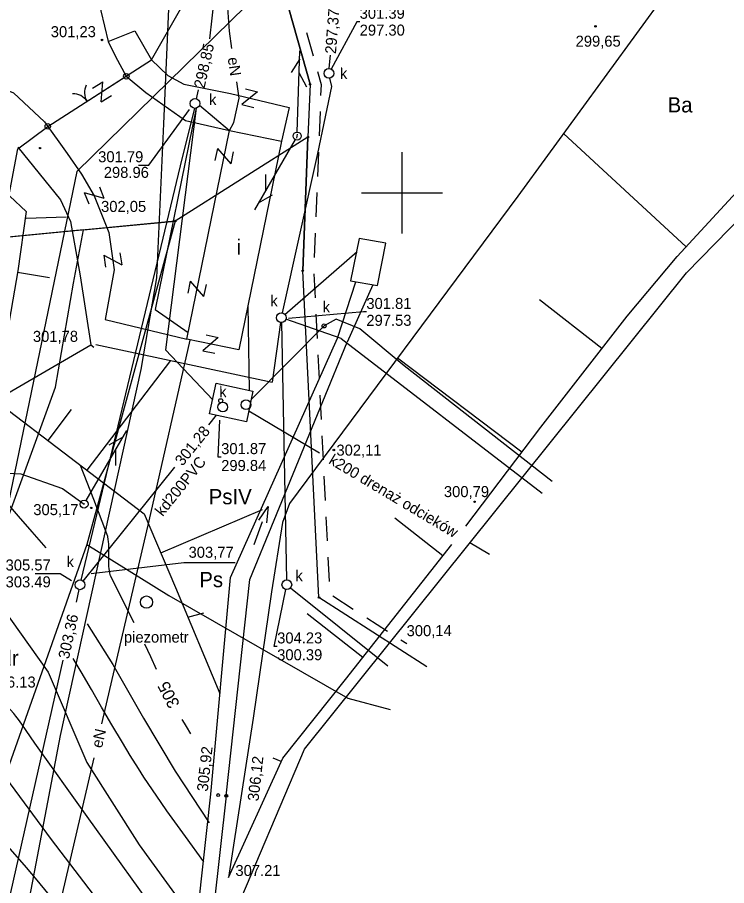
# Model space of a CAD drawing. Extents: x 7477803 to 7478145, y 5500698 to 5500984.
# Drawn here: x 7478026.3 to 7478070, y 5500757.3 to 5500810.8 of the extents above; entities that cross this region are included whole.
import ezdxf

# ---------------------------------------------------------------- set-up
doc = ezdxf.new("R2010")
doc.units = 0
for name, color, linetype in [('203-Punkt załamania granicy działki nie stabilizowany', 7, 'Continuous'), ('budynek', 7, 'Continuous'), ('e_opisy', 7, 'Continuous'), ('e_Proj', 7, 'Continuous'), ('eNN', 7, 'Continuous'), ('funkcja_kondygnacja', 7, 'Continuous'), ('gr_dzialki', 7, 'Continuous'), ('gr_klasy', 7, 'Continuous'), ('gr_uzytek', 7, 'Continuous'), ('k', 7, 'Continuous'), ('k_elem_naziemne', 7, 'Continuous'), ('k_opis', 7, 'Continuous'), ('k_rzedne', 7, 'Continuous'), ('kraweznik', 7, 'Continuous'), ('nazwa_cieku', 7, 'Continuous'), ('ogr_symb', 7, 'Continuous'), ('ogr_w_skali', 7, 'Continuous'), ('opis_klasy', 7, 'Continuous'), ('opis_uzytek', 7, 'Continuous'), ('pkt_wys', 7, 'Continuous'), ('pob_gr_obrebu', 7, 'Continuous'), ('przehaczenie', 7, 'Continuous'), ('przepust', 7, 'Continuous'), ('robocza38', 7, 'Continuous'), ('robocza49', 7, 'Continuous'), ('rowy', 7, 'Continuous'), ('schody', 7, 'Continuous'), ('skarp_wypel', 7, 'Continuous'), ('skarpa_gora', 7, 'Continuous'), ('t', 7, 'Continuous'), ('t_slupy', 7, 'Continuous'), ('w', 7, 'Continuous'), ('warst_ciagla', 7, 'Continuous'), ('warst_opis', 7, 'Continuous'), ('warst_pogrub', 7, 'Continuous'), ('warst_przeryw', 7, 'Continuous'), ('zakresy', 7, 'Continuous')]:
    doc.layers.add(name, color=color, linetype=linetype)

# ---------------------------------------------------------------- blocks, each defined once
blk = doc.blocks.new('203')
blk.add_circle((0, 0), 0.045)
blk = doc.blocks.new('993')
at = {"layer": 'nazwa_cieku'}
for p, q in [((0, 0), (1.5, 0)), ((1.5, 0.25), (2.5, 0)), ((2.5, 0), (1.5, -0.25))]:
    blk.add_line(p, q, dxfattribs=at)
blk = doc.blocks.new('506')
at = {"layer": 'robocza38'}
blk.add_circle((0, 0), 0.3, dxfattribs=at)
blk = doc.blocks.new('506_5')
at = {"layer": 'k_elem_naziemne'}
blk.add_circle((0, 0), 0.3, dxfattribs=at)
blk = doc.blocks.new('506_5_3')
at = {"layer": 'k_elem_naziemne'}
blk.add_circle((0, 0), 0.3, dxfattribs=at)
blk = doc.blocks.new('501_5')
at = {"layer": 'k_elem_naziemne'}
blk.add_circle((0, 0), 0.125, dxfattribs=at)
blk.add_circle((0, 0), 0.125, dxfattribs=at)
blk = doc.blocks.new('511_5_2')
at = {"layer": 't_slupy'}
blk.add_circle((0, 0), 0.25, dxfattribs=at)
blk = doc.blocks.new('SUPT01')
at = {"layer": 't_slupy'}
for p, q in [((5, 0), (105, 0)), ((60.7, -10), (78, 0)), ((95.3, 0), (78, 10))]:
    blk.add_line(p, q, dxfattribs=at)
blk = doc.blocks.new('SUPT1')
at = {"layer": 't_slupy', "xscale": 0.05000000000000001, "yscale": 0.05000000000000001}
blk.add_blockref('SUPT01', (0, 0), dxfattribs=at)
blk = doc.blocks.new('140')
at = {"layer": 'pkt_wys'}
blk.add_circle((0, 0), 0.045, dxfattribs=at)
blk.add_circle((0, 0), 0.045, dxfattribs=at)
blk = doc.blocks.new('991')
at = {"layer": 'przehaczenie'}
for p, q in [((-0.375, 0.5), (0.375, 0.5)), ((-0.375, -0.5), (0.375, 0.5)), ((-0.375, -0.5), (0.375, -0.5))]:
    blk.add_line(p, q, dxfattribs=at)
blk = doc.blocks.new('801_2')
at = {"layer": 'pkt_wys'}
blk.add_circle((0, 0), 0.09, dxfattribs=at)
blk.add_circle((0, 0), 0.09, dxfattribs=at)
blk = doc.blocks.new('991_5')
at = {"layer": 'przehaczenie'}
blk.add_lwpolyline([(-0.38, 0.5), (0.38, 0.5), (-0.38, -0.5), (0.38, -0.5)], dxfattribs=at)
blk = doc.blocks.new('991_5_1')
at = {"layer": 'przehaczenie'}
blk.add_lwpolyline([(-0.38, 0.5), (0.38, 0.5), (-0.38, -0.5), (0.38, -0.5)], dxfattribs=at)

msp = doc.modelspace()

# ---------------------------------------------------------------- linework, layer by layer
at = {"layer": 'budynek'}
msp.add_lwpolyline([(7478042.571, 5500803.187), (7478039.938, 5500790.318), (7478036.74, 5500790.972), (7478039.373, 5500803.842)], close=True, dxfattribs=at)
at = {"layer": 'e_Proj'}
msp.add_lwpolyline([(7478085.721, 5500828.46), (7478062.59, 5500828.394), (7478057.723, 5500828.457), (7478045.093, 5500816.16), (7478029.949, 5500801.309), (7478024.948, 5500777.245), (7478020.357, 5500757.697), (7478013.921, 5500735.554), (7478010.536, 5500720.256)], dxfattribs=at)
at = {"layer": 'eNN'}
for points in [[(7478039.511, 5500808.891), (7478039.356, 5500809.972), (7478039.208, 5500812.294), (7478038.785, 5500813.23), (7478038.592, 5500815.458), (7478038.326, 5500817.428), (7478038.16, 5500821.296), (7478038.14, 5500823.204)], [(7478039.373, 5500803.842), (7478039.627, 5500804.338), (7478039.95, 5500805.838), (7478039.805, 5500806.845)], [(7478031.501, 5500767.257), (7478034.41, 5500779.777), (7478036.943, 5500790.925)], [(7478021.084, 5500721.798), (7478022.348, 5500727.709), (7478025.636, 5500742.267), (7478028.577, 5500754.673), (7478031.014, 5500765.159)]]:
    msp.add_lwpolyline(points, dxfattribs=at)
at = {"layer": 'gr_dzialki'}
for points in [[(7478044.33, 5500806.69), (7478040.64, 5500819.82)], [(7478044.33, 5500806.69), (7478044.2, 5500803.44)], [(7478044.2, 5500803.44), (7478036.02, 5500798.26)], [(7478044.2, 5500803.44), (7478043.88, 5500795.19)], [(7478036.02, 5500798.26), (7478004.67, 5500795.23)], [(7478044.88, 5500775.05), (7478043.88, 5500795.19)], [(7478051.52, 5500770.782), (7478044.88, 5500775.05)]]:
    msp.add_lwpolyline(points, dxfattribs=at)
at = {"layer": 'gr_klasy'}
for points in [[(7478044.2, 5500803.44), (7478036.02, 5500798.26)], [(7478043.88, 5500795.19), (7478044.2, 5500803.44)], [(7478036.02, 5500798.26), (7478030.57, 5500778.31)], [(7478030.37, 5500797.71), (7478012.78, 5500796.01)], [(7478029.75, 5500794.44), (7478030.37, 5500797.71)], [(7478044.88, 5500775.05), (7478043.88, 5500795.19)], [(7478028.63, 5500788.01), (7478029.75, 5500794.44)], [(7478025.09, 5500778.3), (7478028.63, 5500788.01)], [(7478030.57, 5500778.31), (7478035.63, 5500775.18)], [(7478035.63, 5500775.18), (7478046.65, 5500768.85)], [(7478051.52, 5500770.782), (7478044.88, 5500775.05)], [(7478046.65, 5500768.85), (7478049.264, 5500768.141)]]:
    msp.add_lwpolyline(points, dxfattribs=at)
at = {"layer": 'gr_uzytek'}
msp.add_line((7478030.37, 5500797.71), (7478036.02, 5500798.26), dxfattribs=at)
for points in [[(7478040.73, 5500827.51), (7478040.64, 5500819.82), (7478044.33, 5500806.69), (7478044.2, 5500803.44)], [(7478030.57, 5500778.31), (7478022.71, 5500756.1), (7478014.63, 5500723.4), (7478013.163, 5500719.326)]]:
    msp.add_lwpolyline(points, dxfattribs=at)
at = {"layer": 'k'}
for p, q in [((7478038.159, 5500809.5), (7478039.543, 5500822.449)), ((7478037.331, 5500805.786), (7478037.455, 5500806.342)), ((7478036.464, 5500802.174), (7478037.227, 5500805.208)), ((7478037.514, 5500805.404), (7478039.373, 5500803.842)), ((7478030.211, 5500776.125), (7478036.464, 5500802.174)), ((7478042.782, 5500792.498), (7478047.226, 5500796.386)), ((7478040.497, 5500793.072), (7478040.571, 5500787.82)), ((7478046.243, 5500791.027), (7478042.84, 5500792.202)), ((7478042.514, 5500792.003), (7478041.989, 5500788.333)), ((7478042.563, 5500792), (7478042.881, 5500776.147)), ((7478046.243, 5500791.027), (7478058.643, 5500781.492)), ((7478040.564, 5500786.567), (7478044.915, 5500783.969)), ((7478038.543, 5500786.289), (7478038.066, 5500785.696)), ((7478035.963, 5500783.079), (7478030.329, 5500776.067)), ((7478030.075, 5500775.541), (7478029.9, 5500774.764)), ((7478029.096, 5500771.195), (7478020.147, 5500731.456))]:
    msp.add_line(p, q, dxfattribs=at)
for points in [[(7478045.516, 5500807.683), (7478045.579, 5500808.489)], [(7478045.674, 5500806.561), (7478045.557, 5500807.072)], [(7478037.316, 5500805.209), (7478034.785, 5500792.8), (7478036.815, 5500791.389)], [(7478037.316, 5500805.209), (7478035.41, 5500790.314), (7478038.326, 5500787.241)], [(7478042.622, 5500792.593), (7478044.811, 5500802.418)], [(7478059.248, 5500782.195), (7478050.132, 5500789.337), (7478047.403, 5500791.622), (7478045.931, 5500792.209), (7478045.195, 5500791.793), (7478040.697, 5500787.257)], [(7478054.189, 5500778.433), (7478055.393, 5500777.714)], [(7478043.13, 5500775.647), (7478049.128, 5500770.831)]]:
    msp.add_lwpolyline(points, dxfattribs=at)
msp.add_lwpolyline([(7478040.807, 5500787.767), (7478040.401, 5500785.888), (7478038.139, 5500786.377), (7478038.546, 5500788.256)], close=True, dxfattribs=at)
at = {"layer": 'k_rzedne'}
for points in [[(7478047.388, 5500810.549), (7478047.208, 5500810.549), (7478045.633, 5500807.628)], [(7478033.752, 5500801.707), (7478034.394, 5500801.708), (7478036.906, 5500805.127)], [(7478047.799, 5500792.657), (7478047.619, 5500792.657), (7478042.99, 5500792.247)], [(7478038.849, 5500783.707), (7478038.669, 5500783.707), (7478038.757, 5500785.987)], [(7478030.827, 5500776.524), (7478036.541, 5500777.199), (7478039.722, 5500777.202)], [(7478027.374, 5500776.536), (7478028.928, 5500776.537), (7478029.631, 5500776.101)], [(7478042.301, 5500772.038), (7478042.12, 5500772.037), (7478042.838, 5500775.544)]]:
    msp.add_lwpolyline(points, dxfattribs=at)
at = {"layer": 'kraweznik'}
for points in [[(7478031.642, 5500818.53), (7478030.948, 5500814.555), (7478031.177, 5500812.591), (7478031.438, 5500811.212), (7478031.879, 5500809.329), (7478032.326, 5500808.404), (7478033.001, 5500807.187), (7478034.212, 5500806.19), (7478036.657, 5500804.456), (7478039.373, 5500803.842)], [(7478031.879, 5500809.329), (7478033.518, 5500809.988), (7478034.551, 5500808.191), (7478035.566, 5500807.231), (7478036.541, 5500806.696), (7478039.431, 5500806.115), (7478043.036, 5500805.258), (7478042.571, 5500803.187)], [(7478021.467, 5500807.475), (7478023.732, 5500807.128), (7478026.054, 5500806.173), (7478027.956, 5500804.381), (7478029.354, 5500802.427), (7478030.248, 5500801.153), (7478031.021, 5500799.823), (7478031.916, 5500797.559), (7478032.259, 5500795.246), (7478031.695, 5500792.194), (7478036.74, 5500790.972)]]:
    msp.add_lwpolyline(points, dxfattribs=at)
at = {"layer": 'ogr_symb'}
for points in [[(7478026.319, 5500802.715), (7478028.17, 5500804.079), (7478034.551, 5500808.191), (7478045.422, 5500827.246), (7478069.852, 5500827.202)], [(7478023.515, 5500787.992), (7478026.319, 5500802.715)]]:
    msp.add_lwpolyline(points, dxfattribs=at)
at = {"layer": 'ogr_w_skali'}
msp.add_line((7478028.159, 5500804.097), (7478033.001, 5500807.187), dxfattribs=at)
for centre in [(7478033.001, 5500807.187), (7478033.001, 5500807.187), (7478028.159, 5500804.097), (7478028.159, 5500804.097)]:
    msp.add_circle(centre, 0.17, dxfattribs=at)
for centre, start, end in [((7478031.423, 5500806.18), 152.5468, 212.5468), ((7478029.737, 5500805.104), 32.5468, 92.5468)]:
    msp.add_arc(centre, 1, start, end, dxfattribs=at)
at = {"layer": 'pob_gr_obrebu'}
for p, q in [((7478044.11, 5500809.883), (7478044.515, 5500808.439)), ((7478044.942, 5500805.007), (7478044.884, 5500803.509)), ((7478044.845, 5500802.509), (7478044.787, 5500801.011)), ((7478044.748, 5500800.011), (7478044.689, 5500798.512)), ((7478044.65, 5500797.513), (7478044.592, 5500796.014)), ((7478044.563, 5500795.015), (7478044.637, 5500793.517)), ((7478044.686, 5500792.518), (7478044.76, 5500791.02)), ((7478044.809, 5500790.021), (7478044.883, 5500788.523)), ((7478044.932, 5500787.524), (7478045.006, 5500786.026)), ((7478045.055, 5500785.027), (7478045.129, 5500783.529)), ((7478045.178, 5500782.53), (7478045.252, 5500781.032)), ((7478045.301, 5500780.033), (7478045.375, 5500778.535)), ((7478045.424, 5500777.536), (7478045.498, 5500776.038)), ((7478045.727, 5500775.144), (7478046.989, 5500774.333)), ((7478047.831, 5500773.792), (7478049.093, 5500772.981)), ((7478049.934, 5500772.441), (7478050.29, 5500772.212))]:
    msp.add_line(p, q, dxfattribs=at)
msp.add_lwpolyline([(7478044.785, 5500807.476), (7478045.007, 5500806.684), (7478044.981, 5500806.007)], dxfattribs=at)
at = {"layer": 'przepust'}
msp.add_line((7478044.811, 5500802.418), (7478045.674, 5500806.561), dxfattribs=at)
at = {"layer": 'robocza49'}
for p, q in [((7478050, 5500797.5), (7478050, 5500802.5)), ((7478047.5, 5500800), (7478052.5, 5500800))]:
    msp.add_line(p, q, dxfattribs=at)
at = {"layer": 'rowy'}
for points in [[(7478038.215, 5500762.918), (7478039.434, 5500776.278), (7478046.029, 5500791.032)], [(7478039.162, 5500762.829), (7478040.613, 5500776.17), (7478046.614, 5500790.79)], [(7478032.121, 5500724.76), (7478033.203, 5500728.553), (7478035.159, 5500737.454), (7478035.602, 5500739.823), (7478036.71, 5500749.297), (7478038.215, 5500762.918)], [(7478039.162, 5500762.829), (7478037.637, 5500749.217), (7478036.508, 5500739.686), (7478036, 5500737.195), (7478034.07, 5500728.353)]]:
    msp.add_lwpolyline(points, dxfattribs=at)
at = {"layer": 'schody'}
for p, q in [((7478046.029, 5500791.032), (7478047.147, 5500794.51)), ((7478048.193, 5500794.327), (7478046.614, 5500790.79))]:
    msp.add_line(p, q, dxfattribs=at)
msp.add_lwpolyline([(7478048.49, 5500794.29), (7478048.999, 5500796.894), (7478047.354, 5500797.175), (7478046.821, 5500794.572)], close=True, dxfattribs=at)
at = {"layer": 'skarp_wypel'}
for p, q in [((7478067.52, 5500796.678), (7478059.952, 5500803.653)), ((7478026.291, 5500795.109), (7478028.258, 5500794.769)), ((7478062.318, 5500790.394), (7478058.468, 5500793.396)), ((7478024.924, 5500787.202), (7478030.818, 5500790.618)), ((7478030.587, 5500782.892), (7478035.74, 5500789.662)), ((7478057.382, 5500784.014), (7478049.716, 5500789.797)), ((7478028.186, 5500784.732), (7478029.632, 5500786.633)), ((7478035.131, 5500777.806), (7478041.401, 5500780.476)), ((7478052.51, 5500777.614), (7478049.557, 5500779.936)), ((7478036.802, 5500773.832), (7478037.788, 5500774.107)), ((7478047.579, 5500771.342), (7478044.152, 5500774.035)), ((7478042.551, 5500764.931), (7478042.061, 5500765.154))]:
    msp.add_line(p, q, dxfattribs=at)
at = {"layer": 'skarpa_gora'}
for p, q in [((7478026.828, 5500798.438), (7478029.295, 5500798.522)), ((7478031.126, 5500790.643), (7478041.989, 5500788.333))]:
    msp.add_line(p, q, dxfattribs=at)
for points in [[(7478069.928, 5500827.203), (7478073.588, 5500822.37), (7478057.135, 5500799.786), (7478043.065, 5500780.842), (7478042.62, 5500779.665), (7478041.951, 5500775.41), (7478040.823, 5500767.601), (7478039.347, 5500758.051)], [(7478053.931, 5500779.44), (7478058.547, 5500785.559), (7478063.881, 5500792.399), (7478066.961, 5500796.071), (7478077.177, 5500807.154), (7478091.611, 5500820.417), (7478081.823, 5500827.284)], [(7478026.319, 5500802.815), (7478028.949, 5500799.569), (7478029.567, 5500798.238), (7478030.156, 5500794.879), (7478030.818, 5500790.618), (7478030.996, 5500790.48)], [(7478025.82, 5500799.793), (7478026.819, 5500798.852), (7478026.304, 5500795.183), (7478024.924, 5500787.202), (7478034.104, 5500780.215), (7478036.041, 5500775.672), (7478038.759, 5500769.132)], [(7478039.347, 5500758.051), (7478039.308, 5500757.793), (7478042.644, 5500765.135), (7478046.518, 5500769.993), (7478053.066, 5500778.32)]]:
    msp.add_lwpolyline(points, dxfattribs=at)
at = {"layer": 't'}
msp.add_lwpolyline([(7478013.952, 5500749.22), (7478016.25, 5500756.094), (7478018.043, 5500762.466), (7478020.822, 5500772.519), (7478021.714, 5500779.89), (7478022.482, 5500781.51), (7478023.011, 5500782.131), (7478024.071, 5500782.682), (7478025.381, 5500782.734), (7478026.491, 5500782.665), (7478029.072, 5500781.778), (7478030.398, 5500780.809)], dxfattribs=at)
at = {"layer": 't_slupy'}
for p, q in [((7478043.518, 5500803.373), (7478043.548, 5500803.623)), ((7478030.423, 5500780.819), (7478030.373, 5500780.799))]:
    msp.add_line(p, q, dxfattribs=at)
at = {"layer": 'w'}
for points in [[(7478035.933, 5500818.954), (7478035.292, 5500804.261), (7478034.872, 5500794.756), (7478033.904, 5500789.105), (7478028.928, 5500766.534)], [(7478028.928, 5500766.534), (7478026.087, 5500751.628), (7478024.78, 5500744.808), (7478022.827, 5500734.611), (7478021.568, 5500727.759), (7478020.307, 5500723.115), (7478018.729, 5500717.357)]]:
    msp.add_lwpolyline(points, dxfattribs=at)
at = {"layer": 'warst_ciagla'}
for points in [[(7478024.645, 5500782.041), (7478025.489, 5500781.057), (7478026.336, 5500780.074), (7478027.186, 5500779.094), (7478028.037, 5500778.115)], [(7478037.782, 5500758.747), (7478036.645, 5500760.321), (7478035.508, 5500761.895), (7478035.144, 5500762.408), (7478034.61, 5500763.186), (7478034.09, 5500763.974), (7478033.749, 5500764.503), (7478033.247, 5500765.303), (7478032.758, 5500766.111), (7478032.115, 5500767.195), (7478031.478, 5500768.282), (7478030.846, 5500769.371), (7478030.214, 5500770.461), (7478029.971, 5500770.877), (7478029.729, 5500771.293)], [(7478037.23, 5500752.292), (7478035.533, 5500754.662), (7478033.837, 5500757.031), (7478030.597, 5500761.551), (7478027.356, 5500766.07), (7478026.557, 5500767.248), (7478026.349, 5500767.535), (7478026.186, 5500767.744), (7478026.058, 5500767.896), (7478025.857, 5500768.115), (7478025.642, 5500768.321), (7478024.845, 5500769.032), (7478024.048, 5500769.742)], [(7478034.133, 5500748.935), (7478033.014, 5500750.407), (7478031.894, 5500751.88), (7478029.426, 5500755.195), (7478028.164, 5500756.83), (7478027.512, 5500757.63), (7478026.839, 5500758.413), (7478025.117, 5500760.359), (7478023.396, 5500762.305)]]:
    msp.add_lwpolyline(points, dxfattribs=at)
at = {"layer": 'warst_pogrub'}
for points in [[(7478033.48, 5500773.479), (7478032.792, 5500774.859), (7478032.105, 5500776.239), (7478032.037, 5500776.396), (7478031.99, 5500776.548), (7478031.957, 5500776.694), (7478031.936, 5500776.833), (7478031.924, 5500776.966), (7478031.914, 5500777.218), (7478031.932, 5500778.12), (7478031.924, 5500778.342), (7478031.91, 5500778.507), (7478031.892, 5500778.629), (7478031.853, 5500778.808), (7478031.797, 5500778.983), (7478030.99, 5500781.083), (7478030.183, 5500783.182)], [(7478034.858, 5500770.618), (7478034.503, 5500771.398), (7478034.142, 5500772.176)], [(7478036.984, 5500766.654), (7478036.717, 5500767.088), (7478036.585, 5500767.305), (7478036.454, 5500767.523)]]:
    msp.add_lwpolyline(points, dxfattribs=at)
at = {"layer": 'warst_przeryw'}
for points in [[(7478024.737, 5500775.282), (7478028.185, 5500770.437), (7478030.56, 5500764.878), (7478033.801, 5500759.808), (7478037.328, 5500754.935)], [(7478030.594, 5500773.437), (7478032.179, 5500770.929), (7478034.061, 5500767.609), (7478036.019, 5500764.338), (7478038.118, 5500761.152)], [(7478023.475, 5500767.116), (7478025.833, 5500763.558), (7478028.366, 5500760.127), (7478030.951, 5500756.73), (7478033.451, 5500753.27)]]:
    msp.add_lwpolyline(points, dxfattribs=at)
at = {"layer": 'zakresy'}
msp.add_lwpolyline([(7477995.059, 5500962.348), (7477983.951, 5500968.084), (7477970.781, 5500968.613), (7477936.09, 5500958.171), (7477930.511, 5500954.336), (7477914.305, 5500958.58), (7477904.32, 5500957.41), (7477897.265, 5500950.868), (7477811.424, 5500829.338), (7477936.003, 5500769.492), (7478008.982, 5500726.585), (7478019.402, 5500721.781), (7478037.95, 5500734.97), (7478039.493, 5500755.094), (7478043.98, 5500765.708), (7478067.545, 5500795.068), (7478092.109, 5500820.25), (7478076.156, 5500837.989), (7478068.105, 5500851.146), (7478061.422, 5500873.298), (7478054.135, 5500876.371), (7478039.669, 5500897.644), (7478026.36, 5500915.23), (7478015.054, 5500927.728)], close=True, dxfattribs=at)

# ---------------------------------------------------------------- block references
at = {"layer": '203-Punkt załamania granicy działki nie stabilizowany'}
for p in [(7478044.33, 5500806.69), (7478044.2, 5500803.44), (7478036.02, 5500798.26), (7478043.88, 5500795.19), (7478044.88, 5500775.05)]:
    msp.add_blockref('203', p, dxfattribs=at)
at = {"layer": 'k_elem_naziemne', "rotation": 0.0626175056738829}
for name, p in [('506_5', (7478045.49, 5500807.364)), ('506_5', (7478037.232, 5500805.508)), ('506_5', (7478042.557, 5500792.3)), ('501_5', (7478045.195, 5500791.793)), ('506_5', (7478038.949, 5500786.795)), ('501_5', (7478038.821, 5500787.182)), ('506_5_3', (7478040.375, 5500786.933)), ('506_5', (7478030.141, 5500775.833)), ('506_5', (7478042.898, 5500775.838))]:
    msp.add_blockref(name, p, dxfattribs=at)
at = {"layer": 'nazwa_cieku', "rotation": 69.71851626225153}
msp.add_blockref('993', (7478040.887, 5500778.326), dxfattribs=at)
at = {"layer": 'pkt_wys', "rotation": 0.0626175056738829}
for name, p in [('140', (7478061.925, 5500810.268)), ('140', (7478031.503, 5500809.422)), ('140', (7478027.689, 5500802.756)), ('140', (7478045.794, 5500784.147)), ('140', (7478054.47, 5500780.954)), ('140', (7478030.84, 5500780.573)), ('801_2', (7478038.662, 5500762.868)), ('801_2', (7478039.162, 5500762.829))]:
    msp.add_blockref(name, p, dxfattribs=at)
at = {"layer": 'przehaczenie'}
for name, p, rotation in [('991', (7478031.503, 5500806.227), 32.80340161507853), ('991_5_1', (7478040.611, 5500805.834), -13.364767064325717), ('991', (7478039.05, 5500802.261), 78.43671887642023), ('991', (7478031.012, 5500799.845), -68.41978876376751), ('991', (7478032.168, 5500795.864), -81.55413403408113), ('991', (7478037.376, 5500794.083), 78.43671887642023), ('991_5', (7478038.189, 5500790.675), -11.563281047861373)]:
    msp.add_blockref(name, p, dxfattribs=dict(at, rotation=rotation))
at = {"layer": 'robocza38', "xscale": 1.2539698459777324, "yscale": 1.2539698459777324, "rotation": 0.06261750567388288}
msp.add_blockref('506', (7478034.243, 5500774.767), dxfattribs=at)
at = {"layer": 't_slupy'}
for name, p, rotation in [('SUPT1', (7478043.533, 5500803.498), 88.1203749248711), ('SUPT1', (7478043.533, 5500803.498), -120.06718458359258), ('511_5_2', (7478043.533, 5500803.498), 0.0626175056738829), ('SUPT1', (7478030.398, 5500780.809), 59.82999235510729), ('511_5_2', (7478030.398, 5500780.809), 0.0626175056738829)]:
    msp.add_blockref(name, p, dxfattribs=dict(at, rotation=rotation))

# ---------------------------------------------------------------- texts
at = {"layer": 'e_opisy'}
for rotation, p in [(278.1004, (7478039.251, 5500808.315)), (76.9209, (7478031.496, 5500765.731))]:
    msp.add_text('eN', height=0.68, rotation=rotation, dxfattribs=at).set_placement(p)
at = {"layer": 'funkcja_kondygnacja'}
msp.add_text('i', height=0.94, rotation=0.0626, dxfattribs=at).set_placement((7478039.794, 5500796.187))
at = {"layer": 'k_elem_naziemne'}
for p in [(7478046.168, 5500807.024), (7478038.106, 5500805.41), (7478041.878, 5500793.005), (7478045.103, 5500792.627), (7478038.729, 5500787.401), (7478029.318, 5500776.922), (7478043.425, 5500776.056)]:
    msp.add_text('k', height=0.68, rotation=0.0626, dxfattribs=at).set_placement(p)
at = {"layer": 'k_opis'}
for s, rotation, p in [('kd200PVC', 51.2167, (7478035.241, 5500780.01)), ('k200 drenaż odcieków', 329.1609, (7478045.428, 5500783.344))]:
    msp.add_text(s, height=0.68, rotation=rotation, dxfattribs=at).set_placement(p)
at = {"layer": 'k_rzedne'}
for s, rotation, p in [('297,37', 85.5397, (7478045.925, 5500808.545)), ('301.39', 0.0626, (7478047.388, 5500810.729)), ('297.30', 0.0626, (7478047.389, 5500809.689)), ('298,85', 77.4336, (7478037.818, 5500806.404)), ('301.79', 0.0626, (7478031.268, 5500801.884)), ('298.96', 0.0626, (7478031.613, 5500800.918)), ('301.81', 0.0626, (7478047.799, 5500792.837)), ('297.53', 0.0626, (7478047.8, 5500791.797)), ('301,28', 51.2167, (7478036.466, 5500783.115)), ('301.87', 0.0626, (7478038.849, 5500783.887)), ('299.84', 0.0626, (7478038.85, 5500782.847)), ('303,77', 0.0626, (7478036.84, 5500777.499)), ('305.57', 0.0626, (7478025.561, 5500776.714)), ('303.49', 0.0626, (7478025.562, 5500775.674)), ('303,36', 77.6019, (7478029.457, 5500771.219)), ('304.23', 0.0626, (7478042.3, 5500772.218)), ('300.39', 0.0626, (7478042.302, 5500771.178))]:
    msp.add_text(s, height=0.68, rotation=rotation, dxfattribs=at).set_placement(p)
at = {"layer": 'opis_klasy'}
msp.add_text('PsIV', height=0.94, dxfattribs=at).set_placement((7478038.081, 5500780.798))
at = {"layer": 'opis_uzytek'}
for s, p in [('Ba', (7478066.372, 5500804.956)), ('Ps', (7478037.5, 5500775.687)), ('dr', (7478025.247, 5500770.849))]:
    msp.add_text(s, height=0.94, dxfattribs=at).set_placement(p)
at = {"layer": 'pkt_wys'}
for s, rotation, p in [('301,23', 0.0626, (7478028.344, 5500809.594)), ('299,65', 0.0626, (7478060.7, 5500809.008)), ('302,05', 0.0626, (7478031.445, 5500798.819)), ('301,78', 0.0626, (7478027.245, 5500790.809)), ('302,11', 0.0626, (7478045.955, 5500783.796)), ('300,79', 0.0626, (7478052.581, 5500781.239)), ('305,17', 0.0626, (7478027.269, 5500780.127)), ('300,14', 0.0626, (7478050.283, 5500772.665)), ('306.13', 0.0626, (7478024.633, 5500769.496)), ('305,92', 83.6947, (7478038.021, 5500763.065)), ('306,12', 83.6069, (7478041.149, 5500762.466)), ('307.21', 0.0626, (7478039.728, 5500757.879))]:
    msp.add_text(s, height=0.68, rotation=rotation, dxfattribs=at).set_placement(p)
at = {"layer": 'robocza38'}
msp.add_text('piezometr', height=0.68, rotation=0.0626, dxfattribs=at).set_placement((7478032.856, 5500772.27))
at = {"layer": 'warst_opis'}
msp.add_text('305', height=0.75, rotation=116.9791, dxfattribs=at).set_placement((7478036.321, 5500768.47))

doc.saveas('drawing.dxf')
